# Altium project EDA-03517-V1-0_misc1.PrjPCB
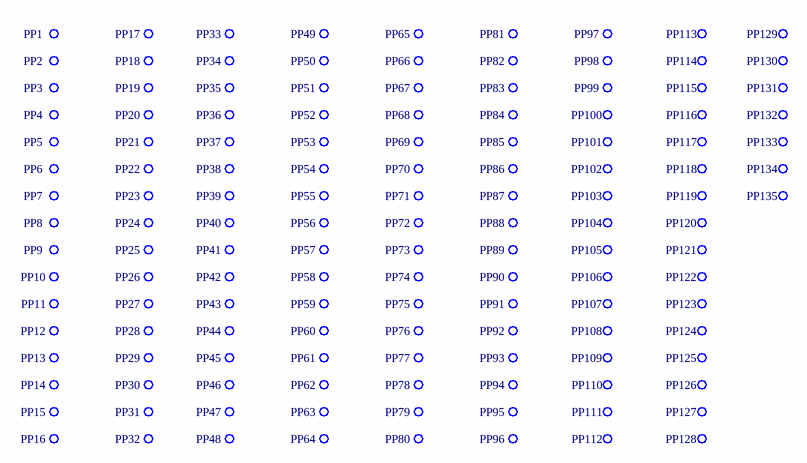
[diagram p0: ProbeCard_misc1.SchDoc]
1 sheet, 135 parts. Net scope: global (net labels, ports and power ports of the same name join across sheets).
Board file: EDA-03517-V1-0_misc1.pcbdoc

## Sheet ProbeCard_misc1.SchDoc: Misc1
size custom portrait; CompanyName: CERN; DrawnBy: JMW; Organization: CERN; Address1: European Organization for Nuclear Research; Address2: CH-1211 Genève 23 - Switzerland; Revision: -; SheetNumber: 1; SheetTotal: 1; EDA_Number: EDA-03517-V1-0; Projet: -; ModifiedBy: -; CreateDate: 28-11-2016; Title2: Probe Card; DivGrp: PH/ESE; Designer: Szymon Kulis

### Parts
PP1  Non Plated Hole  [MTG120]  (value not drawn)
PP2  Non Plated Hole  [MTG120]  (value not drawn)
PP3  Non Plated Hole  [MTG120]  (value not drawn)
PP4  Non Plated Hole  [MTG120]  (value not drawn)
PP5  Non Plated Hole  [MTG120]  (value not drawn)
PP6  Non Plated Hole  [MTG120]  (value not drawn)
PP7  Non Plated Hole  [MTG120]  (value not drawn)
PP8  Non Plated Hole  [MTG120]  (value not drawn)
PP9  Non Plated Hole  [MTG120]  (value not drawn)
PP10  Non Plated Hole  [MTG120]  (value not drawn)
PP11  Non Plated Hole  [MTG120]  (value not drawn)
PP12  Non Plated Hole  [MTG120]  (value not drawn)
PP13  Non Plated Hole  [MTG120]  (value not drawn)
PP14  Non Plated Hole  [MTG120]  (value not drawn)
PP15  Non Plated Hole  [MTG120]  (value not drawn)
PP16  Non Plated Hole  [MTG120]  (value not drawn)
PP17  Non Plated Hole  [MTG120]  (value not drawn)
PP18  Non Plated Hole  [MTG120]  (value not drawn)
PP19  Non Plated Hole  [MTG120]  (value not drawn)
PP20  Non Plated Hole  [MTG120]  (value not drawn)
PP21  Non Plated Hole  [MTG120]  (value not drawn)
PP22  Non Plated Hole  [MTG120]  (value not drawn)
PP23  Non Plated Hole  [MTG120]  (value not drawn)
PP24  Non Plated Hole  [MTG120]  (value not drawn)
PP25  Non Plated Hole  [MTG120]  (value not drawn)
PP26  Non Plated Hole  [MTG120]  (value not drawn)
PP27  Non Plated Hole  [MTG120]  (value not drawn)
PP28  Non Plated Hole  [MTG120]  (value not drawn)
PP29  Non Plated Hole  [MTG120]  (value not drawn)
PP30  Non Plated Hole  [MTG120]  (value not drawn)
PP31  Non Plated Hole  [MTG120]  (value not drawn)
PP32  Non Plated Hole  [MTG120]  (value not drawn)
PP33  Non Plated Hole  [MTG120]  (value not drawn)
PP34  Non Plated Hole  [MTG120]  (value not drawn)
PP35  Non Plated Hole  [MTG120]  (value not drawn)
PP36  Non Plated Hole  [MTG120]  (value not drawn)
PP37  Non Plated Hole  [MTG120]  (value not drawn)
PP38  Non Plated Hole  [MTG120]  (value not drawn)
PP39  Non Plated Hole  [MTG120]  (value not drawn)
PP40  Non Plated Hole  [MTG120]  (value not drawn)
PP41  Non Plated Hole  [MTG120]  (value not drawn)
PP42  Non Plated Hole  [MTG120]  (value not drawn)
PP43  Non Plated Hole  [MTG120]  (value not drawn)
PP44  Non Plated Hole  [MTG120]  (value not drawn)
PP45  Non Plated Hole  [MTG120]  (value not drawn)
PP46  Non Plated Hole  [MTG120]  (value not drawn)
PP47  Non Plated Hole  [MTG120]  (value not drawn)
PP48  Non Plated Hole  [MTG120]  (value not drawn)
PP49  Non Plated Hole  [MTG120]  (value not drawn)
PP50  Non Plated Hole  [MTG120]  (value not drawn)
PP51  Non Plated Hole  [MTG120]  (value not drawn)
PP52  Non Plated Hole  [MTG120]  (value not drawn)
PP53  Non Plated Hole  [MTG120]  (value not drawn)
PP54  Non Plated Hole  [MTG120]  (value not drawn)
PP55  Non Plated Hole  [MTG120]  (value not drawn)
PP56  Non Plated Hole  [MTG120]  (value not drawn)
PP57  Non Plated Hole  [MTG120]  (value not drawn)
PP58  Non Plated Hole  [MTG120]  (value not drawn)
PP59  Non Plated Hole  [MTG120]  (value not drawn)
PP60  Non Plated Hole  [MTG120]  (value not drawn)
PP61  Non Plated Hole  [MTG120]  (value not drawn)
PP62  Non Plated Hole  [MTG120]  (value not drawn)
PP63  Non Plated Hole  [MTG120]  (value not drawn)
PP64  Non Plated Hole  [MTG120]  (value not drawn)
PP65  Non Plated Hole  [MTG120]  (value not drawn)
PP66  Non Plated Hole  [MTG120]  (value not drawn)
PP67  Non Plated Hole  [MTG120]  (value not drawn)
PP68  Non Plated Hole  [MTG120]  (value not drawn)
PP69  Non Plated Hole  [MTG120]  (value not drawn)
PP70  Non Plated Hole  [MTG120]  (value not drawn)
PP71  Non Plated Hole  [MTG120]  (value not drawn)
PP72  Non Plated Hole  [MTG120]  (value not drawn)
PP73  Non Plated Hole  [MTG120]  (value not drawn)
PP74  Non Plated Hole  [MTG120]  (value not drawn)
PP75  Non Plated Hole  [MTG120]  (value not drawn)
PP76  Non Plated Hole  [MTG120]  (value not drawn)
PP77  Non Plated Hole  [MTG120]  (value not drawn)
PP78  Non Plated Hole  [MTG120]  (value not drawn)
PP79  Non Plated Hole  [MTG120]  (value not drawn)
PP80  Non Plated Hole  [MTG120]  (value not drawn)
PP81  Non Plated Hole  [MTG120]  (value not drawn)
PP82  Non Plated Hole  [MTG120]  (value not drawn)
PP83  Non Plated Hole  [MTG120]  (value not drawn)
PP84  Non Plated Hole  [MTG120]  (value not drawn)
PP85  Non Plated Hole  [MTG120]  (value not drawn)
PP86  Non Plated Hole  [MTG120]  (value not drawn)
PP87  Non Plated Hole  [MTG120]  (value not drawn)
PP88  Non Plated Hole  [MTG120]  (value not drawn)
PP89  Non Plated Hole  [MTG120]  (value not drawn)
PP90  Non Plated Hole  [MTG120]  (value not drawn)
PP91  Non Plated Hole  [MTG120]  (value not drawn)
PP92  Non Plated Hole  [MTG120]  (value not drawn)
PP93  Non Plated Hole  [MTG120]  (value not drawn)
PP94  Non Plated Hole  [MTG120]  (value not drawn)
PP95  Non Plated Hole  [MTG120]  (value not drawn)
PP96  Non Plated Hole  [MTG120]  (value not drawn)
PP97  Non Plated Hole  [MTG120]  (value not drawn)
PP98  Non Plated Hole  [MTG120]  (value not drawn)
PP99  Non Plated Hole  [MTG120]  (value not drawn)
PP100  Non Plated Hole  [MTG120]  (value not drawn)
PP101  Non Plated Hole  [MTG120]  (value not drawn)
PP102  Non Plated Hole  [MTG120]  (value not drawn)
PP103  Non Plated Hole  [MTG120]  (value not drawn)
PP104  Non Plated Hole  [MTG120]  (value not drawn)
PP105  Non Plated Hole  [MTG120]  (value not drawn)
PP106  Non Plated Hole  [MTG120]  (value not drawn)
PP107  Non Plated Hole  [MTG120]  (value not drawn)
PP108  Non Plated Hole  [MTG120]  (value not drawn)
PP109  Non Plated Hole  [MTG120]  (value not drawn)
PP110  Non Plated Hole  [MTG120]  (value not drawn)
PP111  Non Plated Hole  [MTG120]  (value not drawn)
PP112  Non Plated Hole  [MTG120]  (value not drawn)
PP113  Non Plated Hole  [MTG120]  (value not drawn)
PP114  Non Plated Hole  [MTG120]  (value not drawn)
PP115  Non Plated Hole  [MTG120]  (value not drawn)
PP116  Non Plated Hole  [MTG120]  (value not drawn)
PP117  Non Plated Hole  [MTG120]  (value not drawn)
PP118  Non Plated Hole  [MTG120]  (value not drawn)
PP119  Non Plated Hole  [MTG120]  (value not drawn)
PP120  Non Plated Hole  [MTG120]  (value not drawn)
PP121  Non Plated Hole  [MTG120]  (value not drawn)
PP122  Non Plated Hole  [MTG120]  (value not drawn)
PP123  Non Plated Hole  [MTG120]  (value not drawn)
PP124  Non Plated Hole  [MTG120]  (value not drawn)
PP125  Non Plated Hole  [MTG120]  (value not drawn)
PP126  Non Plated Hole  [MTG120]  (value not drawn)
PP127  Non Plated Hole  [MTG120]  (value not drawn)
PP128  Non Plated Hole  [MTG120]  (value not drawn)
PP129  Non Plated Hole  [MTG120]  (value not drawn)
PP130  Non Plated Hole  [MTG120]  (value not drawn)
PP131  Non Plated Hole  [MTG120]  (value not drawn)
PP132  Non Plated Hole  [MTG120]  (value not drawn)
PP133  Non Plated Hole  [MTG120]  (value not drawn)
PP134  Non Plated Hole  [MTG120]  (value not drawn)
PP135  Non Plated Hole  [MTG120]  (value not drawn)

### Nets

Not connected (* = marked no-connect by the designer): PP1 1; PP2 1; PP3 1; PP4 1; PP5 1; PP6 1; PP7 1; PP8 1; PP9 1; PP10 1; PP11 1; PP12 1; PP13 1; PP14 1; PP15 1; PP16 1; PP17 1; PP18 1; PP19 1; PP20 1; PP21 1; PP22 1; PP23 1; PP24 1; PP25 1; PP26 1; PP27 1; PP28 1; PP29 1; PP30 1; PP31 1; PP32 1; PP33 1; PP34 1; PP35 1; PP36 1; PP37 1; PP38 1; PP39 1; PP40 1; PP41 1; PP42 1; PP43 1; PP44 1; PP45 1; PP46 1; PP47 1; PP48 1; PP49 1; PP50 1; PP51 1; PP52 1; PP53 1; PP54 1; PP55 1; PP56 1; PP57 1; PP58 1; PP59 1; PP60 1; PP61 1; PP62 1; PP63 1; PP64 1; PP65 1; PP66 1; PP67 1; PP68 1; PP69 1; PP70 1; PP71 1; PP72 1; PP73 1; PP74 1; PP75 1; PP76 1; PP77 1; PP78 1; PP79 1; PP80 1; PP81 1; PP82 1; PP83 1; PP84 1; PP85 1; PP86 1; PP87 1; PP88 1; PP89 1; PP90 1; PP91 1; PP92 1; PP93 1; PP94 1; PP95 1; PP96 1; PP97 1; PP98 1; PP99 1; PP100 1; PP101 1; PP102 1; PP103 1; PP104 1; PP105 1; PP106 1; PP107 1; PP108 1; PP109 1; PP110 1; PP111 1; PP112 1; PP113 1; PP114 1; PP115 1; PP116 1; PP117 1; PP118 1; PP119 1; PP120 1; PP121 1; PP122 1; PP123 1; PP124 1; PP125 1; PP126 1; PP127 1; PP128 1; PP129 1; PP130 1; PP131 1; PP132 1; PP133 1; PP134 1; PP135 1

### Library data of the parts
PP1-PP135 = NON-PLATED_HOLE1.2: Single Terminal Socket; Part Description: Non Plated Through Hole: Hole Dia.=1.2mm; Mounted: No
